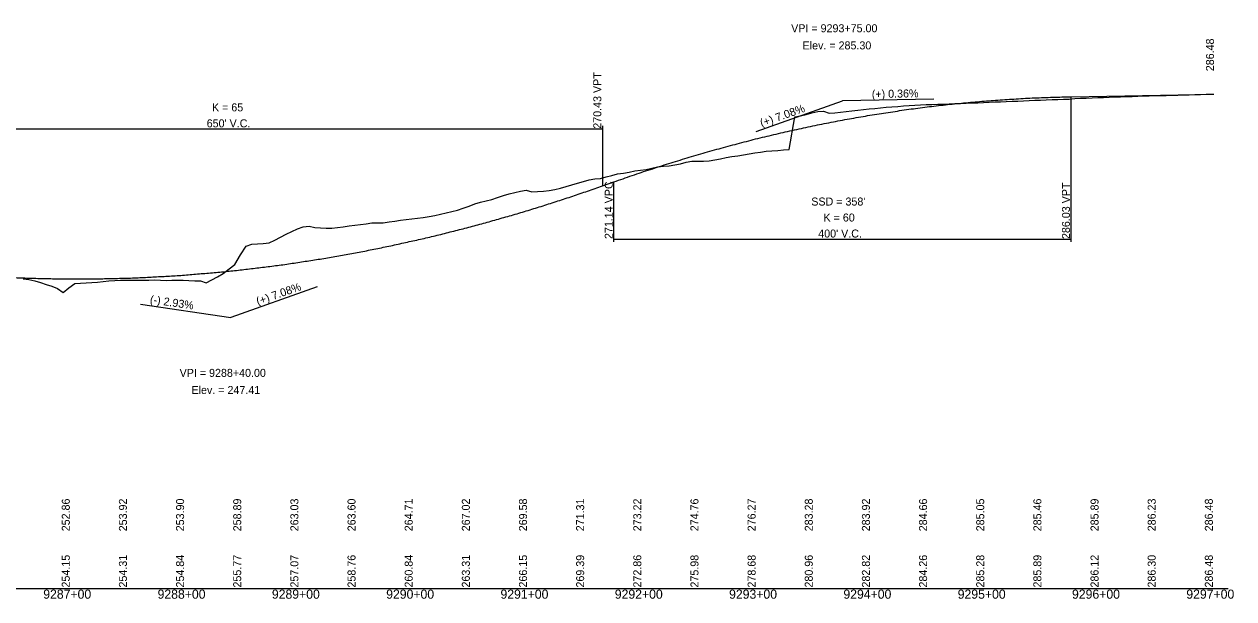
# Model space of a CAD drawing. Extents: x 1838386 to 1955906, y 719739 to 834437.
# Drawn here: x 1922691 to 1923749, y 735980 to 736483 of the extents above; entities that cross this region are included whole.
import ezdxf

# ---------------------------------------------------------------- set-up
doc = ezdxf.new("R2010")
doc.units = 0
for name, color, linetype in [('RD_DDB_GradeTX', 7, 'Continuous'), ('RD_DDB_Profile_EX', 7, 'Continuous'), ('RD_DDB_Profile_Lbl', 7, 'Continuous'), ('RD_DDB_Profile_PR', 7, 'Continuous'), ('RD_DDB_StaTX', 7, 'Continuous'), ('RD_DDB_StripGrade', 7, 'Continuous'), ('RD_DDB_VCLbl', 7, 'Continuous'), ('RD_GPK_Profile_Cell', 7, 'Continuous')]:
    doc.layers.add(name, color=color, linetype=linetype)

msp = doc.modelspace()

# ---------------------------------------------------------------- linework, layer by layer
at = {"layer": 'RD_DDB_GradeTX'}
for p, q in [((1923331.3, 736389), (1923406.7, 736415.7)), ((1923486.7, 736417.1), (1923406.7, 736415.7)), ((1922947.1, 736252.9), (1922871.7, 736226.2)), ((1922792.6, 736237.8), (1922871.7, 736226.2))]:
    msp.add_line(p, q, dxfattribs=at)
at = {"layer": 'RD_DDB_Profile_EX'}
for points in [[(1923050, 736315.5), (1923055, 736316.6), (1923060, 736317.7), (1923065, 736318.9), (1923070, 736320), (1923075, 736321.8), (1923080, 736323.6), (1923085, 736325.5), (1923090, 736327.1), (1923095, 736328.3), (1923100, 736329.4), (1923105, 736331.1), (1923110, 736332.8), (1923115, 736334.3), (1923120, 736335.5), (1923125, 736336.8), (1923130, 736337.5), (1923135, 736336.1), (1923140, 736336.3), (1923145, 736336.7), (1923150, 736337.4), (1923155, 736338.1), (1923160, 736339.4), (1923165, 736340.8), (1923170, 736342.3), (1923175, 736343.7), (1923180, 736345.2), (1923185, 736346.6), (1923190, 736347.5), (1923195, 736347.8), (1923200, 736349.1), (1923205, 736350.5), (1923210, 736351.9), (1923215, 736352.5), (1923220, 736353.3), (1923225, 736354.6), (1923230, 736355), (1923235, 736355.6), (1923240, 736356.9), (1923245, 736358.1), (1923250, 736358.5), (1923255, 736358.9), (1923260, 736359.6), (1923265, 736360.7), (1923270, 736361.9), (1923275, 736363), (1923280, 736363), (1923285, 736362.9), (1923290, 736363.2), (1923295, 736364.2), (1923300, 736365.1), (1923305, 736366.1), (1923310, 736366.9), (1923315, 736367.6), (1923320, 736368.4), (1923325, 736369.4), (1923330, 736370.3), (1923335, 736370.9), (1923340, 736371.6), (1923345, 736372), (1923350, 736372.3), (1923355, 736372.7), (1923360, 736373.2), (1923365, 736401.6), (1923370, 736402.6), (1923375, 736403.8), (1923380, 736405.1), (1923385, 736406.4), (1923390, 736406.8), (1923395, 736404.8), (1923400, 736405.3), (1923405, 736405.9), (1923410, 736406.4), (1923415, 736407), (1923420, 736407.5), (1923425, 736408), (1923430, 736408.6), (1923435, 736409.1), (1923440, 736409.6), (1923445, 736410.1), (1923450, 736410.5), (1923455, 736410.8), (1923460, 736411.2), (1923465, 736411.6), (1923470, 736411.9), (1923475, 736412.2), (1923480, 736412.4), (1923485, 736412.6), (1923490, 736412.7), (1923495, 736412.9), (1923500, 736413.1), (1923505, 736413.3), (1923510, 736413.5), (1923515, 736413.7), (1923520, 736413.9), (1923525, 736414.1), (1923530, 736414.3), (1923535, 736414.5), (1923540, 736414.7), (1923545, 736414.9), (1923550, 736415.1)], [(1923550, 736415.1), (1923555, 736415.3), (1923560, 736415.5), (1923565, 736415.7), (1923570, 736416), (1923575, 736416.2), (1923580, 736416.4), (1923585, 736416.6), (1923590, 736416.8), (1923595, 736417), (1923600, 736417.1), (1923605, 736417.3), (1923610, 736417.8), (1923615, 736417.9), (1923620, 736418.1), (1923625, 736418.3), (1923630, 736418.5), (1923635, 736418.7), (1923640, 736418.9), (1923645, 736419.1), (1923650, 736419.3), (1923655, 736419.5), (1923660, 736419.6), (1923665, 736419.8), (1923670, 736420), (1923675, 736420.1), (1923680, 736420.3), (1923685, 736420.4), (1923690, 736420.5), (1923695, 736420.7), (1923700, 736420.8), (1923705, 736420.9), (1923710, 736421.1), (1923715, 736421.2), (1923720, 736421.3), (1923725, 736421.4), (1923730, 736421.5), (1923731.7, 736421.6)], [(1922690, 736259.9), (1922695, 736259.3), (1922700, 736258.3), (1922705, 736256.7), (1922710, 736255.1), (1922715, 736253.5), (1922720, 736251.4), (1922725, 736248), (1922730, 736252.2), (1922735, 736255.9), (1922740, 736256.3), (1922745, 736256.6), (1922750, 736256.8), (1922755, 736257.2), (1922760, 736257.7), (1922765, 736258.1), (1922770, 736258.4), (1922775, 736258.7), (1922780, 736258.8), (1922785, 736258.7), (1922790, 736258.7), (1922795, 736258.7), (1922800, 736258.8), (1922805, 736259), (1922810, 736258.9), (1922815, 736258.6), (1922820, 736258.7), (1922825, 736258.9), (1922830, 736258.7), (1922835, 736258.4), (1922840, 736258.2), (1922845, 736258.1), (1922850, 736256.4), (1922855, 736259.1), (1922860, 736261.8), (1922865, 736264.6), (1922870, 736268.8), (1922875, 736272.6), (1922880, 736281), (1922885, 736288.6), (1922890, 736290.2), (1922895, 736290.5), (1922900, 736290.8), (1922905, 736291.5), (1922910, 736293.7), (1922915, 736296.4), (1922920, 736299), (1922925, 736301.5), (1922930, 736303.6), (1922935, 736305.6), (1922940, 736306.1), (1922945, 736305), (1922950, 736304.7), (1922955, 736304.4), (1922960, 736304.3), (1922965, 736304.9), (1922970, 736305.6), (1922975, 736306.2), (1922980, 736306.9), (1922985, 736307.6), (1922990, 736308.2), (1922995, 736308.9), (1923000, 736309.1), (1923005, 736308.9), (1923010, 736309.8), (1923015, 736310.5), (1923020, 736311.2), (1923025, 736311.8), (1923030, 736312.5), (1923035, 736313.1), (1923040, 736313.7), (1923045, 736314.4), (1923050, 736315.5)]]:
    msp.add_lwpolyline(points, dxfattribs=at)
at = {"layer": 'RD_DDB_Profile_PR'}
for p, q in [((1923606.7, 736419.3), (1923731.7, 736421.6)), ((1923196.7, 736341.3), (1923206.7, 736344.8))]:
    msp.add_line(p, q, dxfattribs=at)
for points in [[(1923206.7, 736344.8), (1923214.7, 736347.6), (1923222.7, 736350.4), (1923230.7, 736353.1), (1923238.7, 736355.7), (1923246.7, 736358.3), (1923254.7, 736360.9), (1923262.7, 736363.3), (1923270.7, 736365.8), (1923278.7, 736368.2), (1923286.7, 736370.5), (1923294.7, 736372.7), (1923302.7, 736375), (1923310.7, 736377.1), (1923318.7, 736379.2), (1923326.7, 736381.3), (1923334.7, 736383.3), (1923342.7, 736385.2), (1923350.7, 736387.1), (1923358.7, 736389), (1923366.7, 736390.7), (1923374.7, 736392.5), (1923382.7, 736394.2), (1923390.7, 736395.8), (1923398.7, 736397.3), (1923406.7, 736398.9), (1923414.7, 736400.3), (1923422.7, 736401.7), (1923430.7, 736403.1), (1923438.7, 736404.4), (1923446.7, 736405.6), (1923454.7, 736406.8), (1923462.7, 736408), (1923470.7, 736409.1), (1923478.7, 736410.1), (1923486.7, 736411.1), (1923494.7, 736412), (1923502.7, 736412.9), (1923510.7, 736413.7), (1923518.7, 736414.4), (1923526.7, 736415.1), (1923534.7, 736415.8), (1923542.7, 736416.4), (1923550.7, 736417), (1923558.7, 736417.4), (1923566.7, 736417.9), (1923574.7, 736418.3), (1923582.7, 736418.6), (1923590.7, 736418.9), (1923598.7, 736419.1), (1923606.7, 736419.3)], [(1922546.7, 736273.8), (1922559.7, 736272), (1922572.7, 736270.3), (1922585.7, 736268.7), (1922598.7, 736267.3), (1922611.7, 736265.9), (1922624.7, 736264.8), (1922637.7, 736263.7), (1922650.7, 736262.8), (1922663.7, 736262), (1922676.7, 736261.3), (1922689.7, 736260.8), (1922702.7, 736260.4), (1922715.7, 736260.1), (1922728.7, 736259.9), (1922741.7, 736259.9), (1922754.7, 736260), (1922767.7, 736260.3), (1922780.7, 736260.6), (1922793.7, 736261.1), (1922806.7, 736261.8), (1922819.7, 736262.5), (1922832.7, 736263.4), (1922845.7, 736264.5), (1922858.7, 736265.6), (1922871.7, 736266.9), (1922884.7, 736268.3), (1922897.7, 736269.9), (1922910.7, 736271.5), (1922923.7, 736273.3), (1922936.7, 736275.3), (1922949.7, 736277.3), (1922962.7, 736279.5), (1922975.7, 736281.9), (1922988.7, 736284.3), (1923001.7, 736286.9), (1923014.7, 736289.6), (1923027.7, 736292.5), (1923040.7, 736295.4), (1923053.7, 736298.5), (1923066.7, 736301.8), (1923079.7, 736305.1), (1923092.7, 736308.6), (1923105.7, 736312.3), (1923118.7, 736316), (1923131.7, 736319.9), (1923144.7, 736323.9), (1923157.7, 736328.1), (1923170.7, 736332.3), (1923183.7, 736336.8), (1923196.7, 736341.3)]]:
    msp.add_spline(points, degree=3, dxfattribs=at)
at = {"layer": 'RD_DDB_VCLbl'}
for p, q in [((1923606.7, 736292.3), (1923606.7, 736419.3)), ((1922546.7, 736391.3), (1923196.7, 736391.3)), ((1923196.7, 736393.8), (1923196.7, 736341.3)), ((1923206.7, 736292.3), (1923206.7, 736344.8)), ((1923206.7, 736294.8), (1923606.7, 736294.8))]:
    msp.add_line(p, q, dxfattribs=at)
at = {"layer": 'RD_GPK_Profile_Cell'}
msp.add_line((1914544, 735989.1), (1923744, 735989.1), dxfattribs=at)

# ---------------------------------------------------------------- texts
at = {"layer": 'RD_DDB_GradeTX'}
for s, rotation, p in [('(+) 0.36%', 1.0406, (1923432.4, 736418.1)), ('(+) 7.08%', 19.4987, (1923336, 736392.7)), ('(+) 7.08%', 19.4987, (1922895.3, 736236.7)), ('(-) 2.93%', 351.6622, (1922800.5, 736238.7))]:
    msp.add_text(s, height=7, rotation=rotation, dxfattribs=at).set_placement(p)
at = {"layer": 'RD_DDB_Profile_Lbl'}
for s, p in [('VPI = 9293+75.00', (1923361.8, 736475.7)), ('Elev. = 285.30', (1923371.8, 736460.7)), ('VPI = 9288+40.00', (1922826.8, 736174.2)), ('Elev. = 247.41', (1922837.2, 736159.2))]:
    msp.add_text(s, height=7, dxfattribs=at).set_placement(p)
msp.add_text('286.48', height=7, rotation=90, dxfattribs=at).set_placement((1923731.7, 736441.6))
at = {"layer": 'RD_DDB_StaTX'}
for s, p in [('9287+00', (1922707.5, 735980.1)), ('9288+00', (1922807.5, 735980.1)), ('9289+00', (1922907.5, 735980.1)), ('9290+00', (1923007.5, 735980.1)), ('9291+00', (1923107.5, 735980.1)), ('9292+00', (1923207.5, 735980.1)), ('9293+00', (1923307.5, 735980.1)), ('9294+00', (1923407.5, 735980.1)), ('9295+00', (1923507.5, 735980.1)), ('9296+00', (1923607.5, 735980.1)), ('9297+00', (1923707.5, 735980.1))]:
    msp.add_text(s, height=8, dxfattribs=at).set_placement(p)
at = {"layer": 'RD_DDB_StripGrade'}
for s, p in [('270.43 VPT', (1923195.7, 736391.3)), ('271.14 VPC', (1923205.7, 736294.8)), ('286.03 VPT', (1923605.7, 736294.8)), ('252.86', (1922730.7, 736039.1)), ('253.92', (1922780.7, 736039.1)), ('253.90', (1922830.7, 736039.1)), ('258.89', (1922880.7, 736039.1)), ('263.03', (1922930.7, 736039.1)), ('263.60', (1922980.7, 736039.1)), ('264.71', (1923030.7, 736039.1)), ('267.02', (1923080.7, 736039.1)), ('269.58', (1923130.7, 736039.1)), ('271.31', (1923180.7, 736039.1)), ('273.22', (1923230.7, 736039.1)), ('274.76', (1923280.7, 736039.1)), ('276.27', (1923330.7, 736039.1)), ('283.28', (1923380.7, 736039.1)), ('283.92', (1923430.7, 736039.1)), ('284.66', (1923480.7, 736039.1)), ('285.05', (1923530.7, 736039.1)), ('285.46', (1923580.7, 736039.1)), ('285.89', (1923630.7, 736039.1)), ('286.23', (1923680.7, 736039.1)), ('286.48', (1923730.7, 736039.1)), ('254.15', (1922730.7, 735989.9)), ('254.31', (1922780.7, 735989.9)), ('254.84', (1922830.7, 735989.9)), ('255.77', (1922880.7, 735989.9)), ('257.07', (1922930.7, 735989.9)), ('258.76', (1922980.7, 735989.9)), ('260.84', (1923030.7, 735989.9)), ('263.31', (1923080.7, 735989.9)), ('266.15', (1923130.7, 735989.9)), ('269.39', (1923180.7, 735989.9)), ('272.86', (1923230.7, 735989.9)), ('275.98', (1923280.7, 735989.9)), ('278.68', (1923330.7, 735989.9)), ('280.96', (1923380.7, 735989.9)), ('282.82', (1923430.7, 735989.9)), ('284.26', (1923480.7, 735989.9)), ('285.28', (1923530.7, 735989.9)), ('285.89', (1923580.7, 735989.9)), ('286.12', (1923630.7, 735989.9)), ('286.30', (1923680.7, 735989.9)), ('286.48', (1923730.7, 735989.9))]:
    msp.add_text(s, height=7, rotation=90, dxfattribs=at).set_placement(p)
at = {"layer": 'RD_DDB_VCLbl'}
for s, p in [('K = 65', (1922855.1, 736406.5)), ("650' V.C.", (1922850.5, 736392.5)), ("SSD = 358'", (1923379.4, 736324.1)), ('K = 60', (1923390.1, 736310.1)), ("400' V.C.", (1923385.5, 736296.1))]:
    msp.add_text(s, height=7, dxfattribs=at).set_placement(p)

doc.saveas('drawing.dxf')
